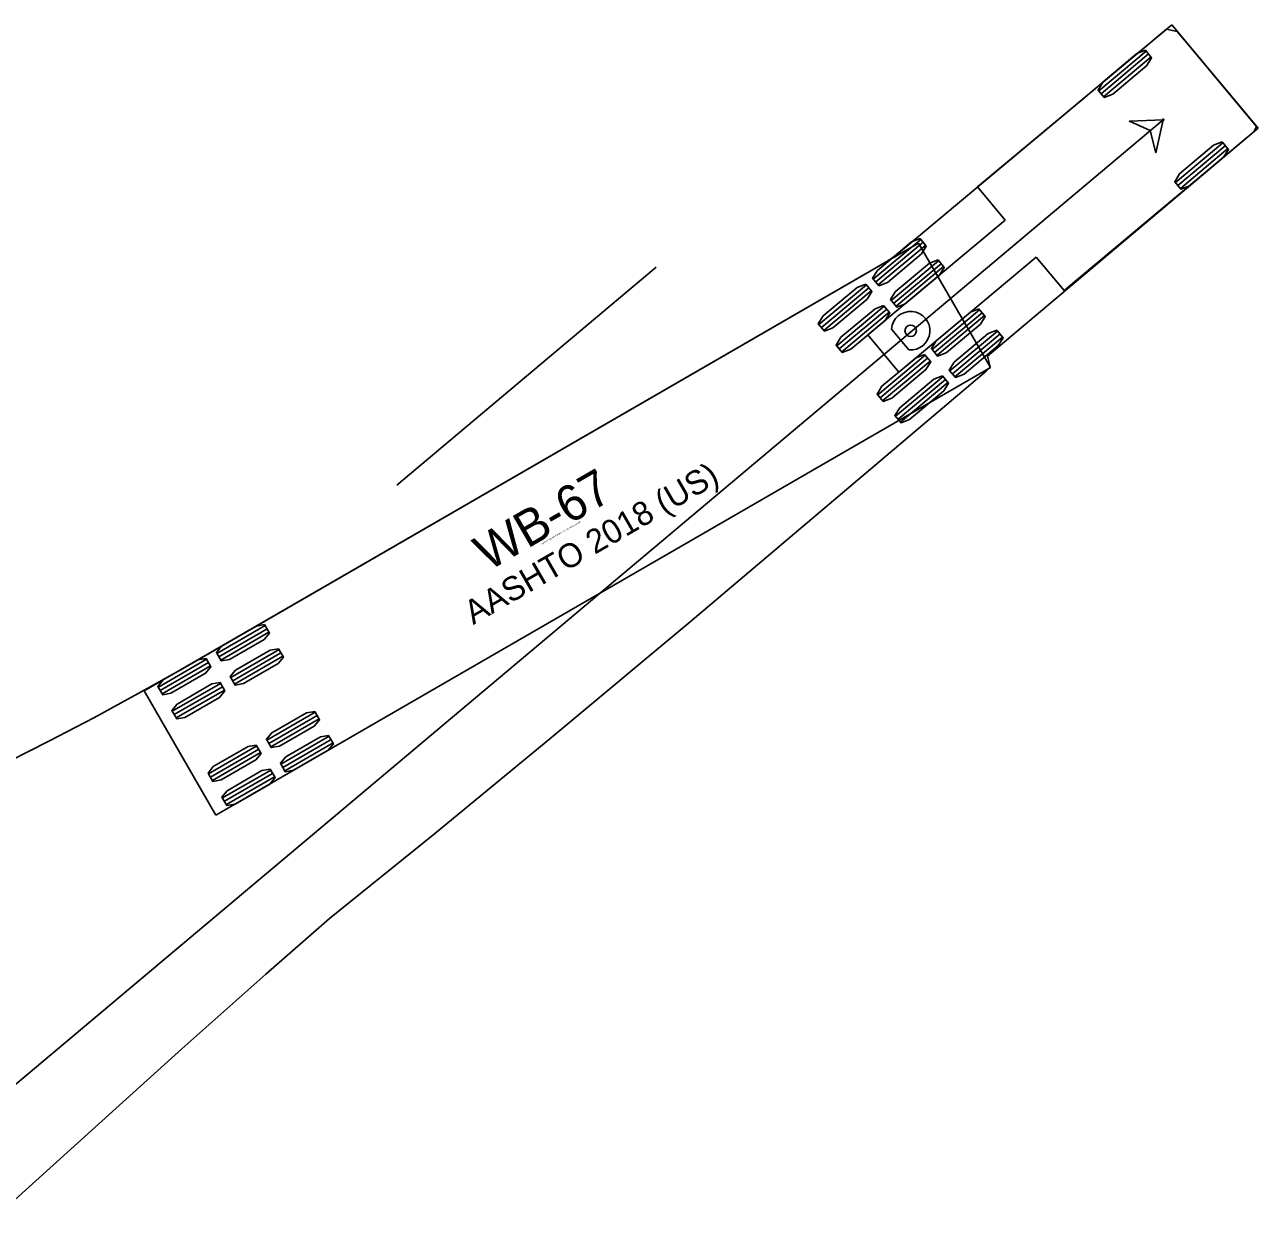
# Model space of a CAD drawing. Extents: x 2175591 to 2194071, y 76570 to 86955.
# Drawn here: x 2192986.5 to 2193059.6, y 86390.5 to 86461.2 of the extents above; entities that cross this region are included whole.
import ezdxf

# ---------------------------------------------------------------- set-up
doc = ezdxf.new("R2010")
doc.units = 0
doc.layers.add('-NOPLT', color=7, linetype='Continuous')

msp = doc.modelspace()

# ---------------------------------------------------------------- linework, layer by layer
at = {"layer": '-NOPLT'}
for p, q in [((2193054.479, 86461.215), (2193042.969, 86451.596)), ((2193059.609, 86455.077), (2193054.479, 86461.215)), ((2193054.479, 86461.215), (2193054.479, 86461.215)), ((2193052.958, 86459.653), (2193050.152, 86457.293)), ((2193053.106, 86459.478), (2193050.299, 86457.118)), ((2193053.253, 86459.302), (2193050.447, 86456.942)), ((2192980.51, 86393.81), (2193053.975, 86455.581)), ((2193048.099, 86445.458), (2193059.609, 86455.077)), ((2193057.503, 86454.219), (2193054.696, 86451.86)), ((2193057.65, 86454.044), (2193054.844, 86451.684)), ((2193057.798, 86453.869), (2193054.991, 86451.509)), ((2193042.969, 86451.596), (2193044.615, 86449.627)), ((2193044.615, 86449.627), (2193036.481, 86442.83)), ((2193039.612, 86448.492), (2193036.798, 86446.141)), ((2193039.759, 86448.316), (2193036.945, 86445.965)), ((2193039.482, 86448.257), (2192993.6, 86421.727)), ((2193039.906, 86448.14), (2193037.092, 86445.789)), ((2193043.736, 86440.899), (2193039.482, 86448.257)), ((2193039.482, 86448.257), (2193039.482, 86448.257)), ((2193040.67, 86447.226), (2193037.857, 86444.875)), ((2193040.817, 86447.05), (2193038.003, 86444.699)), ((2193040.964, 86446.874), (2193038.15, 86444.523)), ((2193038.32, 86440.63), (2193046.453, 86447.427)), ((2193046.453, 86447.427), (2193048.099, 86445.458)), ((2193008.585, 86433.93), (2193023.932, 86446.835)), ((2193036.389, 86445.799), (2193033.576, 86443.448)), ((2193036.536, 86445.623), (2193033.723, 86443.272)), ((2193036.683, 86445.447), (2193033.87, 86443.096)), ((2193037.447, 86444.533), (2193034.634, 86442.181)), ((2193037.594, 86444.357), (2193034.781, 86442.006)), ((2193037.741, 86444.181), (2193034.928, 86441.83)), ((2193043.096, 86444.323), (2193040.283, 86441.972)), ((2193043.243, 86444.147), (2193040.43, 86441.796)), ((2193043.39, 86443.971), (2193040.577, 86441.62)), ((2193036.481, 86442.83), (2193038.32, 86440.63)), ((2193037.874, 86443.178), (2193038.91, 86441.938)), ((2193044.154, 86443.057), (2193041.341, 86440.706)), ((2193044.301, 86442.881), (2193041.488, 86440.53)), ((2193044.448, 86442.705), (2193041.635, 86440.354)), ((2193039.873, 86441.63), (2193037.06, 86439.278)), ((2193040.02, 86441.454), (2193037.207, 86439.103)), ((2193040.167, 86441.278), (2193037.354, 86438.927)), ((2192997.854, 86414.369), (2193043.736, 86440.899)), ((2193040.931, 86440.364), (2193038.118, 86438.012)), ((2193041.078, 86440.188), (2193038.265, 86437.836)), ((2193041.225, 86440.012), (2193038.412, 86437.661)), ((2193000.77, 86425.608), (2192997.913, 86423.957)), ((2193000.885, 86425.41), (2192998.028, 86423.758)), ((2193000.999, 86425.212), (2192998.142, 86423.56)), ((2192997.307, 86423.606), (2192994.45, 86421.954)), ((2193001.596, 86424.18), (2192998.739, 86422.528)), ((2193001.71, 86423.982), (2192998.854, 86422.33)), ((2193001.825, 86423.783), (2192998.968, 86422.131)), ((2192997.422, 86423.408), (2192994.565, 86421.756)), ((2192997.536, 86423.209), (2192994.68, 86421.557)), ((2192998.133, 86422.178), (2192995.276, 86420.526)), ((2192993.6, 86421.727), (2192997.854, 86414.369)), ((2192998.248, 86421.979), (2192995.391, 86420.327)), ((2192998.362, 86421.781), (2192995.506, 86420.129)), ((2193003.74, 86420.472), (2193000.883, 86418.82)), ((2193003.855, 86420.274), (2193000.998, 86418.622)), ((2193003.969, 86420.075), (2193001.112, 86418.423)), ((2193000.277, 86418.47), (2192997.42, 86416.818)), ((2193004.566, 86419.044), (2193001.709, 86417.392)), ((2193004.68, 86418.845), (2193001.824, 86417.193)), ((2193004.795, 86418.647), (2193001.938, 86416.995)), ((2193000.392, 86418.271), (2192997.535, 86416.619)), ((2193000.506, 86418.073), (2192997.65, 86416.421)), ((2193001.103, 86417.041), (2192998.246, 86415.389)), ((2193001.218, 86416.843), (2192998.361, 86415.191)), ((2193001.332, 86416.644), (2192998.476, 86414.993))]:
    msp.add_line(p, q, dxfattribs=at)
for points in [[(2192985.591, 86417.539), (2192987.968, 86418.748), (2192990.622, 86420.146), (2192993.257, 86421.58), (2192995.873, 86423.048), (2193037.507, 86447.115), (2193038.056, 86447.482), (2193054.176, 86460.941), (2193054.794, 86460.806), (2193055.232, 86460.303), (2193059.51, 86455.19), (2193059.369, 86454.888), (2193043.572, 86441.563), (2193043.715, 86440.93), (2193043.485, 86440.688), (2193036.636, 86434.869), (2193025.946, 86425.83), (2193017.765, 86418.985), (2193010.816, 86413.266), (2193004.585, 86408.248), (2193000.824, 86404.953), (2192995.841, 86400.525), (2192984.705, 86390.475)], [(2193053.975, 86455.581), (2193051.977, 86455.492), (2193053.209, 86454.937), (2193053.544, 86453.628), (2193053.975, 86455.581)]]:
    msp.add_lwpolyline(points, dxfattribs=at)
for points in [[(2193052.922, 86459.696), (2193053.29, 86459.259), (2193053.008, 86458.796), (2193050.987, 86457.097), (2193050.483, 86456.899), (2193050.115, 86457.337), (2193050.397, 86457.799), (2193052.418, 86459.498)], [(2193053.975, 86455.581), (2193051.977, 86455.492), (2193053.209, 86454.937), (2193053.544, 86453.628)], [(2193057.466, 86454.263), (2193057.834, 86453.825), (2193057.552, 86453.363), (2193055.532, 86451.664), (2193055.028, 86451.465), (2193054.66, 86451.903), (2193054.942, 86452.366), (2193056.962, 86454.065)], [(2193039.576, 86448.536), (2193039.942, 86448.097), (2193039.659, 86447.635), (2193037.633, 86445.942), (2193037.129, 86445.746), (2193036.762, 86446.184), (2193037.045, 86446.646), (2193039.071, 86448.339)], [(2193040.634, 86447.27), (2193041, 86446.831), (2193040.717, 86446.369), (2193038.691, 86444.676), (2193038.187, 86444.479), (2193037.82, 86444.918), (2193038.103, 86445.38), (2193040.129, 86447.073)], [(2193036.353, 86445.842), (2193036.72, 86445.403), (2193036.436, 86444.942), (2193034.41, 86443.249), (2193033.906, 86443.052), (2193033.539, 86443.491), (2193033.823, 86443.953), (2193035.848, 86445.645)], [(2193037.411, 86444.576), (2193037.778, 86444.137), (2193037.494, 86443.676), (2193035.469, 86441.983), (2193034.964, 86441.786), (2193034.597, 86442.225), (2193034.881, 86442.686), (2193036.906, 86444.379)], [(2193043.06, 86444.367), (2193043.427, 86443.928), (2193043.143, 86443.466), (2193041.117, 86441.773), (2193040.613, 86441.576), (2193040.246, 86442.015), (2193040.53, 86442.477), (2193042.555, 86444.17)], [(2193044.118, 86443.101), (2193044.485, 86442.662), (2193044.201, 86442.2), (2193042.175, 86440.507), (2193041.671, 86440.31), (2193041.304, 86440.749), (2193041.588, 86441.211), (2193043.613, 86442.904)], [(2193039.837, 86441.673), (2193040.204, 86441.234), (2193039.92, 86440.773), (2193037.895, 86439.08), (2193037.39, 86438.883), (2193037.023, 86439.322), (2193037.307, 86439.783), (2193039.333, 86441.476)], [(2193040.895, 86440.407), (2193041.262, 86439.968), (2193040.978, 86439.507), (2193038.953, 86437.814), (2193038.448, 86437.617), (2193038.082, 86438.056), (2193038.365, 86438.517), (2193040.391, 86440.21)], [(2193000.741, 86425.658), (2193001.028, 86425.162), (2193000.714, 86424.782), (2192998.657, 86423.593), (2192998.171, 86423.511), (2192997.885, 86424.006), (2192998.198, 86424.386), (2193000.255, 86425.576)], [(2193001.567, 86424.229), (2193001.854, 86423.734), (2193001.54, 86423.354), (2192999.483, 86422.164), (2192998.997, 86422.082), (2192998.71, 86422.577), (2192999.024, 86422.958), (2193001.081, 86424.147)], [(2192997.279, 86423.655), (2192997.565, 86423.16), (2192997.251, 86422.78), (2192995.194, 86421.59), (2192994.708, 86421.508), (2192994.422, 86422.003), (2192994.735, 86422.384), (2192996.792, 86423.573)], [(2192998.105, 86422.227), (2192998.391, 86421.732), (2192998.077, 86421.351), (2192996.02, 86420.162), (2192995.534, 86420.08), (2192995.248, 86420.575), (2192995.561, 86420.955), (2192997.618, 86422.145)], [(2193003.711, 86420.521), (2193003.998, 86420.026), (2193003.684, 86419.645), (2193001.627, 86418.456), (2193001.141, 86418.374), (2193000.855, 86418.869), (2193001.168, 86419.25), (2193003.225, 86420.439)], [(2193004.537, 86419.093), (2193004.824, 86418.598), (2193004.51, 86418.217), (2193002.453, 86417.028), (2193001.967, 86416.946), (2193001.681, 86417.441), (2193001.994, 86417.821), (2193004.051, 86419.011)], [(2193000.249, 86418.519), (2193000.535, 86418.024), (2193000.221, 86417.643), (2192998.164, 86416.454), (2192997.678, 86416.372), (2192997.392, 86416.867), (2192997.705, 86417.247), (2192999.762, 86418.437)], [(2193001.075, 86417.09), (2193001.361, 86416.595), (2193001.047, 86416.215), (2192998.99, 86415.025), (2192998.504, 86414.943), (2192998.218, 86415.439), (2192998.531, 86415.819), (2193000.588, 86417.008)]]:
    msp.add_lwpolyline(points, close=True, dxfattribs=at)
for centre, radius in [((2193053.975, 86455.581), 0.0417), ((2193039.012, 86443.076), 0.34)]:
    msp.add_circle(centre, radius, dxfattribs=at)
msp.add_arc((2193039.012, 86443.076), 1.143, 264.88595, 174.88595, dxfattribs=at)

# ---------------------------------------------------------------- texts
for s, height, p in [('AASHTO 2018 (US)', 1.41667, (2193013.1, 86425.63)), ('WB-67', 2.125, (2193013.984, 86428.801)), ('(c) 2024 Transoft Solutions, Inc. All rights reserved.', 0.085, (2193017.183, 86430.405))]:
    msp.add_text(s, height=height, rotation=30.0376, dxfattribs=at).set_placement(p)

doc.saveas('drawing.dxf')
